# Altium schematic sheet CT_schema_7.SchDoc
size 278 x 170 mm
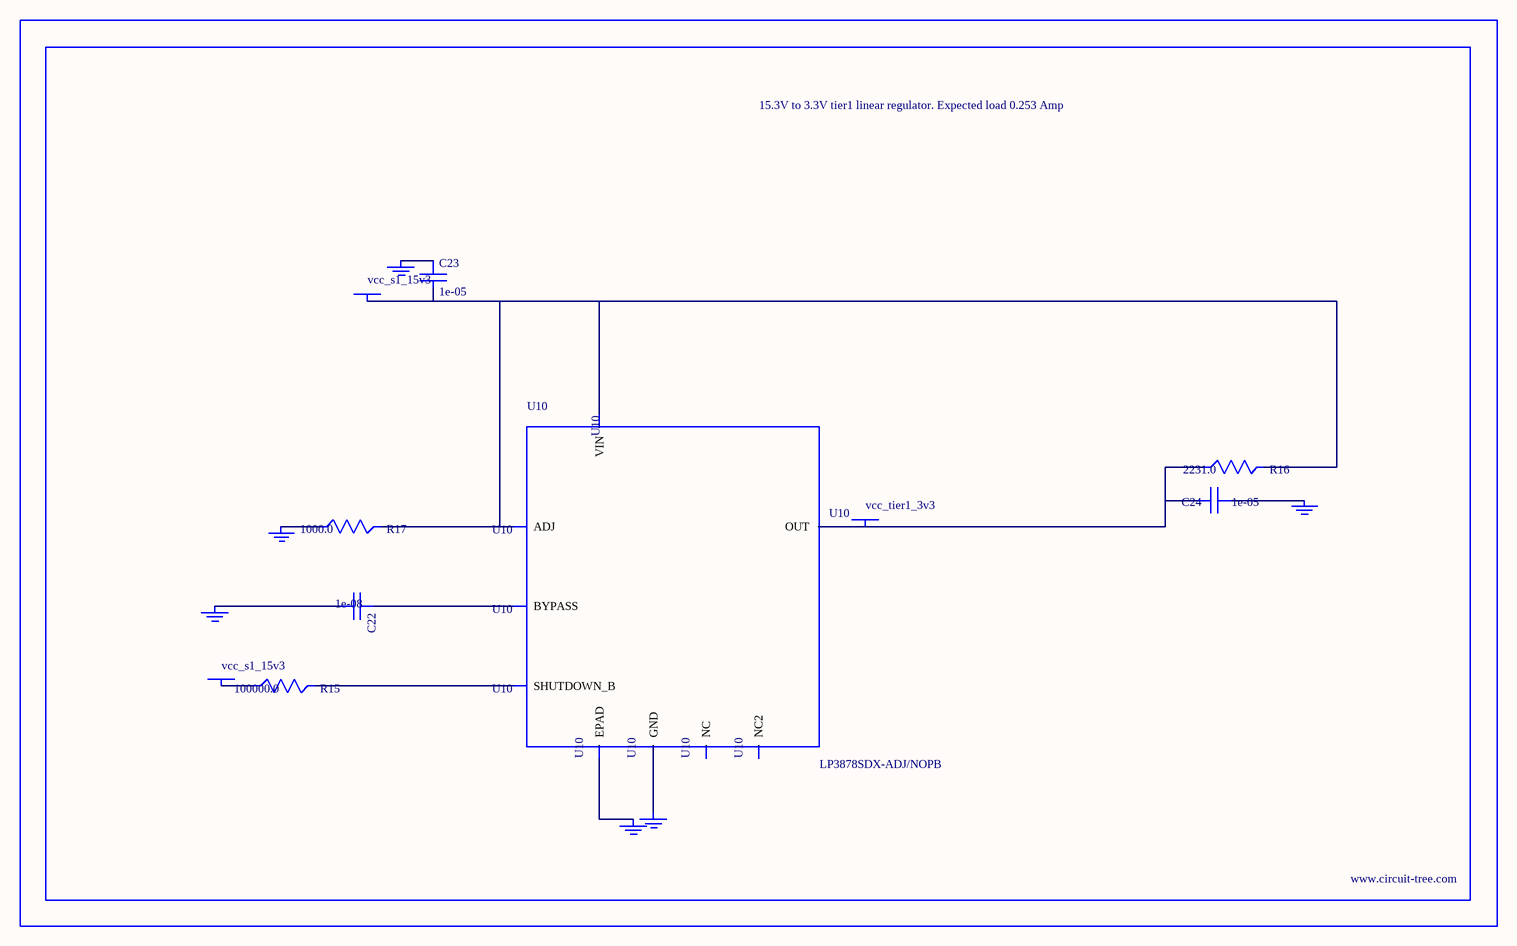
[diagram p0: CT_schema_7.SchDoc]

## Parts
BORDER6  (no value)
C22  1e-08  [C0402]
C23  1e-05  [C1210]
C24  1e-05  [C1210]
GND_INSTANCE_6_0  (no value)
GND_INSTANCE_6_1  (no value)
GND_INSTANCE_6_2  (no value)
GND_INSTANCE_6_3  (no value)
GND_INSTANCE_6_4  (no value)
GND_INSTANCE_6_5  (no value)
POWER_INSTANCE_6_0  vcc_s1_15v3
POWER_INSTANCE_6_1  vcc_s1_15v3
POWER_INSTANCE_6_2  vcc_tier1_3v3
R15  100000.0  [R0603]
R16  2231.0  [R0603]
R17  1000.0  [R0603]
U10  LP3878SDX-ADJ/NOPB  [WSON-8]

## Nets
NetC22_1: C22.1 U10.1(BYPASS)
NetC22_2: C22.2 GND_INSTANCE_6_0.0(GND)
NetC23_1: C23.1 GND_INSTANCE_6_1.0(GND)
NetC23_2: C23.2 POWER_INSTANCE_6_0.0(PWR) R16.2 R17.2 U10.4(VIN) U10.6(ADJ)
NetC24_1: C24.1 GND_INSTANCE_6_2.0(GND)
NetC24_2: C24.2 POWER_INSTANCE_6_2.0(PWR) R16.1 U10.5(OUT)
NetGND_INSTANCE_6_3_0: GND_INSTANCE_6_3.0(GND) R17.1
NetGND_INSTANCE_6_4_0: GND_INSTANCE_6_4.0(GND) U10.PAD(EPAD)
NetGND_INSTANCE_6_5_0: GND_INSTANCE_6_5.0(GND) U10.3(GND)
NetPOWER_INSTANCE_6_1_0: POWER_INSTANCE_6_1.0(PWR) R15.1
NetR15_2: R15.2 U10.8(SHUTDOWN_B)

Not connected (* = marked no-connect by the designer): U10 2(NC) 7(NC2)

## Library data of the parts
BORDER6 = BORDER_PAGE6
C22 = C0402C103K3RAC
C23 = C1210C106K5PACTU
C24 = GRM32DR61E106MA12L
GND_INSTANCE_6_0-GND_INSTANCE_6_5 = GND
POWER_INSTANCE_6_0-POWER_INSTANCE_6_2 = PWR
R15 = RC0603JR-07100KL
R16 = R16
R17 = RC0603JR-071KL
